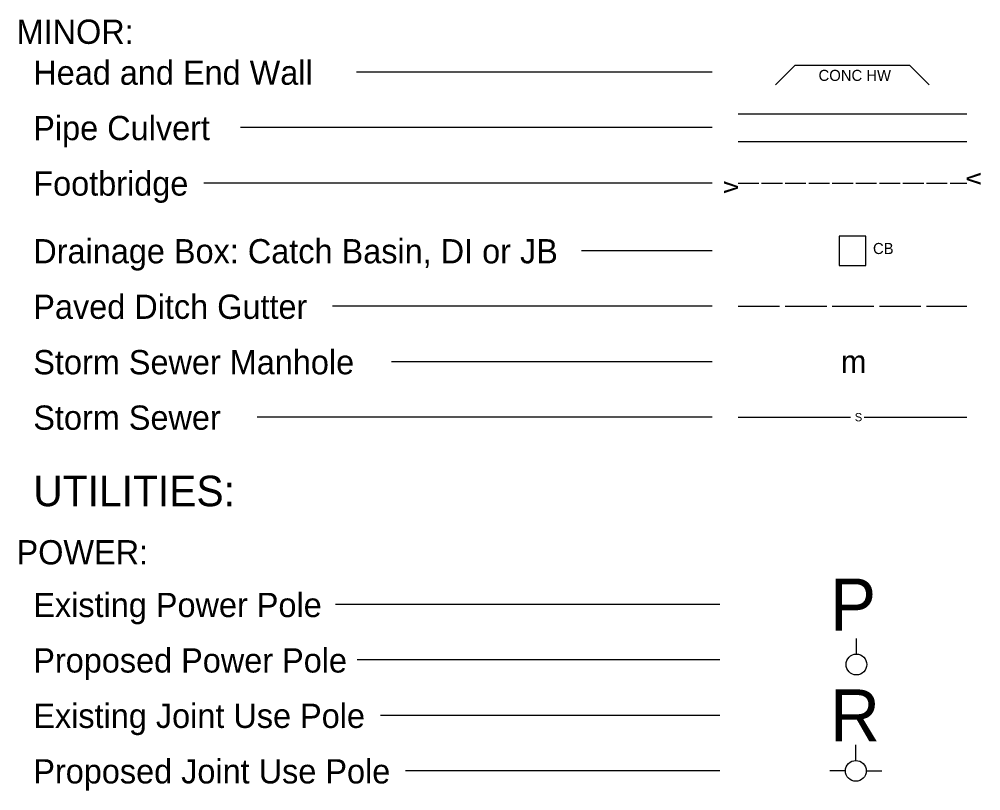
# Model space of a CAD drawing. Extents: x 2014488 to 2016172, y 399324 to 400424.
# Drawn here: x 2015417.8 to 2015764.7, y 399861.9 to 400140.1 of the extents above; entities that cross this region are included whole.
import ezdxf

# ---------------------------------------------------------------- set-up
doc = ezdxf.new("R2010")
doc.units = 0
doc.layers.add('Sheet Symbology CELL', color=7, linetype='Continuous')

msp = doc.modelspace()

# ---------------------------------------------------------------- linework, layer by layer
at = {"layer": 'Sheet Symbology CELL'}
for p, q in [((2015690.71, 400116.48), (2015697.78, 400123.55)), ((2015697.78, 400123.55), (2015739.03, 400123.55)), ((2015739.03, 400123.55), (2015746.11, 400116.48)), ((2015667.86, 400121.05), (2015539.56, 400121.05)), ((2015677.16, 400106.05), (2015759.66, 400106.05)), ((2015667.86, 400101.05), (2015497.67, 400101.05)), ((2015677.16, 400096.05), (2015759.66, 400096.05)), ((2015667.86, 400081.05), (2015484.38, 400081.05)), ((2015677.16, 400081.05), (2015684.66, 400081.05)), ((2015685.66, 400081.05), (2015693.16, 400081.05)), ((2015694.16, 400081.05), (2015701.66, 400081.05)), ((2015702.66, 400081.05), (2015710.16, 400081.05)), ((2015711.16, 400081.05), (2015718.66, 400081.05)), ((2015719.66, 400081.05), (2015727.16, 400081.05)), ((2015728.16, 400081.05), (2015735.66, 400081.05)), ((2015736.66, 400081.05), (2015744.16, 400081.05)), ((2015745.16, 400081.05), (2015752.66, 400081.05)), ((2015753.66, 400081.05), (2015759.66, 400081.05)), ((2015667.86, 400056.62), (2015620.66, 400056.62)), ((2015667.86, 400036.62), (2015530.91, 400036.62)), ((2015677.16, 400036.62), (2015692.16, 400036.62)), ((2015694.16, 400036.62), (2015709.16, 400036.62)), ((2015711.16, 400036.62), (2015726.16, 400036.62)), ((2015728.16, 400036.62), (2015743.16, 400036.62)), ((2015745.16, 400036.62), (2015759.66, 400036.62)), ((2015667.86, 400016.62), (2015552.18, 400016.62)), ((2015667.86, 399996.62), (2015503.66, 399996.62)), ((2015677.16, 399996.62), (2015717.68, 399996.62)), ((2015722.68, 399996.62), (2015759.66, 399996.62)), ((2015670.65, 399929.04), (2015531.95, 399929.04)), ((2015719.87, 399911.15), (2015719.87, 399916.77)), ((2015670.65, 399909.04), (2015539.73, 399909.04)), ((2015670.65, 399889.04), (2015548.13, 399889.04)), ((2015719.66, 399872.8), (2015719.66, 399878.42)), ((2015670.65, 399869.04), (2015557.13, 399869.04)), ((2015715.91, 399869.05), (2015710.28, 399869.05)), ((2015723.41, 399869.05), (2015729.03, 399869.05))]:
    msp.add_line(p, q, dxfattribs=at)
msp.add_lwpolyline([(2015713.6, 400051.31), (2015723.21, 400051.31), (2015723.21, 400061.95), (2015713.6, 400061.95)], close=True, dxfattribs=at)
for centre in [(2015719.87, 399907.4), (2015719.66, 399869.04)]:
    msp.add_circle(centre, 3.75, dxfattribs=at)

# ---------------------------------------------------------------- texts
for s, height, rotation, p in [('MINOR:', 8.75, 360, (2015416.87, 400131.26)), ('Head and End Wall', 8.75, 360, (2015422.9, 400116.5)), ('CONC HW', 4, 360, (2015706.21, 400117.89)), ('Pipe Culvert', 8.75, 360, (2015422.9, 400096.52)), ('Footbridge', 8.75, 360, (2015422.91, 400076.52)), ('v', 6.6, 270.2409, (2015759.65, 400084.79)), ('v', 6.6, 89.7591, (2015677.15, 400077.32)), ('Drainage Box: Catch Basin, DI or JB', 8.75, 360, (2015422.91, 400052.09)), ('CB', 4, 360, (2015725.85, 400055.45)), ('Paved Ditch Gutter', 8.75, 360, (2015422.91, 400032.07)), ('Storm Sewer Manhole', 8.75, 360, (2015422.91, 400012.07)), ('m', 8.25, 360, (2015714.28, 400012.5)), ('Storm Sewer', 8.75, 360, (2015422.91, 399992.07)), ('S', 3, 360, (2015719.28, 399995.12)), ('UTILITIES:', 11, 360, (2015422.9, 399964.49)), ('POWER:', 8.75, 360, (2015416.87, 399943.5)), ('P', 18.75, 360, (2015710.28, 399919.66)), ('Existing Power Pole', 8.75, 360, (2015422.91, 399924.5)), ('Proposed Power Pole', 8.75, 360, (2015422.91, 399904.5)), ('R', 18.75, 360, (2015710.28, 399879.66)), ('Existing Joint Use Pole', 8.75, 360, (2015422.91, 399884.51)), ('Proposed Joint Use Pole', 8.75, 360, (2015422.92, 399864.5))]:
    msp.add_text(s, height=height, rotation=rotation, dxfattribs=at).set_placement(p)

doc.saveas('drawing.dxf')
